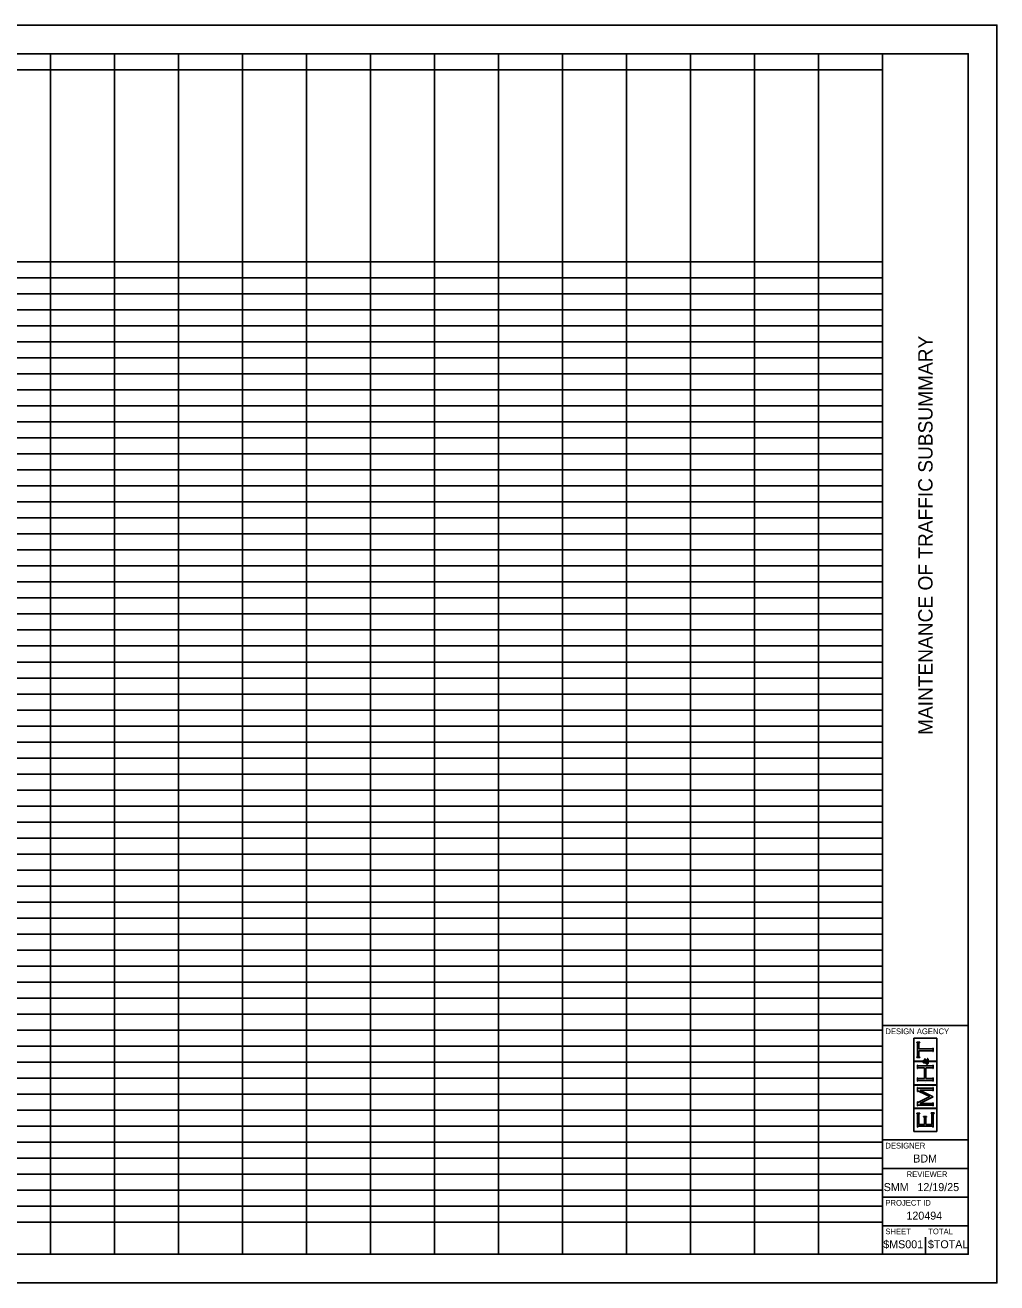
# Model space of a CAD drawing. Extents: x 0 to 34, y 0 to 22.
# Drawn here: x 17 to 34, y 0 to 22 of the extents above; entities that cross this region are included whole.
import ezdxf

# ---------------------------------------------------------------- set-up
doc = ezdxf.new("R2010")
doc.units = 0
for name, color, linetype in [('Default', 7, 'Continuous'), ('SH_Border', 7, 'Continuous'), ('SH_Cut_Line', 7, 'Continuous'), ('SH_Data', 7, 'Continuous')]:
    doc.layers.add(name, color=color, linetype=linetype)

msp = doc.modelspace()

# ---------------------------------------------------------------- linework, layer by layer
at = {"layer": 'Default'}
for p, q in [((1.5, 21.5), (32, 21.5)), ((17.442, 21.5), (17.442, 0.5)), ((18.562, 21.5), (18.562, 0.5)), ((19.681, 21.5), (19.681, 0.5)), ((20.801, 21.5), (20.801, 0.5)), ((21.921, 21.5), (21.921, 0.5)), ((23.041, 21.5), (23.041, 0.5)), ((24.161, 21.5), (24.161, 0.5)), ((25.281, 21.5), (25.281, 0.5)), ((26.401, 21.5), (26.401, 0.5)), ((27.521, 21.5), (27.521, 0.5)), ((28.64, 21.5), (28.64, 0.5)), ((29.76, 21.5), (29.76, 0.5)), ((30.88, 21.5), (30.88, 0.5)), ((32, 21.5), (32, 0.5)), ((5.123, 21.22), (32, 21.22)), ((5.123, 17.86), (32, 17.86)), ((1.5, 17.58), (32, 17.58)), ((1.5, 17.3), (32, 17.3)), ((1.5, 17.02), (32, 17.02)), ((1.5, 16.74), (32, 16.74)), ((1.5, 16.46), (32, 16.46)), ((1.5, 16.18), (32, 16.18)), ((1.5, 15.9), (32, 15.9)), ((1.5, 15.62), (32, 15.62)), ((1.5, 15.34), (32, 15.34)), ((1.5, 15.06), (32, 15.06)), ((1.5, 14.78), (32, 14.78)), ((1.5, 14.5), (32, 14.5)), ((1.5, 14.22), (32, 14.22)), ((1.5, 13.94), (32, 13.94)), ((1.5, 13.66), (32, 13.66)), ((1.5, 13.38), (32, 13.38)), ((1.5, 13.1), (32, 13.1)), ((1.5, 12.82), (32, 12.82)), ((1.5, 12.54), (32, 12.54)), ((1.5, 12.26), (32, 12.26)), ((1.5, 11.98), (32, 11.98)), ((1.5, 11.7), (32, 11.7)), ((1.5, 11.42), (32, 11.42)), ((1.5, 11.14), (32, 11.14)), ((1.5, 10.86), (32, 10.86)), ((1.5, 10.58), (32, 10.58)), ((1.5, 10.3), (32, 10.3)), ((1.5, 10.02), (32, 10.02)), ((1.5, 9.74), (32, 9.74)), ((1.5, 9.46), (32, 9.46)), ((1.5, 9.18), (32, 9.18)), ((1.5, 8.9), (32, 8.9)), ((1.5, 8.62), (32, 8.62)), ((1.5, 8.34), (32, 8.34)), ((1.5, 8.06), (32, 8.06)), ((1.5, 7.78), (32, 7.78)), ((1.5, 7.5), (32, 7.5)), ((1.5, 7.22), (32, 7.22)), ((1.5, 6.94), (32, 6.94)), ((1.5, 6.66), (32, 6.66)), ((1.5, 6.38), (32, 6.38)), ((1.5, 6.1), (32, 6.1)), ((1.5, 5.82), (32, 5.82)), ((1.5, 5.54), (32, 5.54)), ((1.5, 5.26), (32, 5.26)), ((1.5, 4.98), (32, 4.98)), ((1.5, 4.7), (32, 4.7)), ((1.5, 4.42), (32, 4.42)), ((1.5, 4.14), (32, 4.14)), ((1.5, 3.86), (32, 3.86)), ((1.5, 3.58), (32, 3.58)), ((1.5, 3.3), (32, 3.3)), ((1.5, 3.02), (32, 3.02)), ((1.5, 2.74), (32, 2.74)), ((1.5, 2.46), (32, 2.46)), ((1.5, 2.18), (32, 2.18)), ((1.5, 1.9), (32, 1.9)), ((1.5, 1.62), (32, 1.62)), ((1.5, 1.34), (32, 1.34)), ((1.5, 1.06), (32, 1.06)), ((1.5, 0.5), (32, 0.5))]:
    msp.add_line(p, q, dxfattribs=at)
at = {"layer": 'SH_Border'}
for p, q in [((32, 0.5), (32, 21.5)), ((32, 4.5), (33.5, 4.5)), ((32, 2.5), (33.5, 2.5)), ((32, 2), (33.5, 2)), ((32, 1.5), (33.5, 1.5)), ((32, 1), (33.5, 1))]:
    msp.add_line(p, q, dxfattribs=at)
msp.add_lwpolyline([(1.5, 21.5), (33.5, 21.5), (33.5, 0.5), (1.5, 0.5)], close=True, dxfattribs=at)
at = {"layer": 'SH_Cut_Line'}
msp.add_lwpolyline([(0, 0), (34, 0), (34, 22), (0, 22)], close=True, dxfattribs=at)
at = {"layer": 'SH_Data'}
for p, q in [((32.952, 4.279), (32.547, 4.279)), ((32.547, 4.279), (32.547, 3.875)), ((32.598, 4.204), (32.598, 4.211)), ((32.598, 4.211), (32.65, 4.211)), ((32.603, 4.203), (32.598, 4.204)), ((32.606, 4.201), (32.603, 4.203)), ((32.608, 4.199), (32.606, 4.201)), ((32.61, 4.196), (32.608, 4.199)), ((32.611, 4.192), (32.61, 4.196)), ((32.611, 4.187), (32.611, 4.192)), ((32.611, 3.968), (32.611, 4.187)), ((32.638, 4.196), (32.637, 4.192)), ((32.637, 4.192), (32.637, 4.187)), ((32.637, 4.187), (32.637, 4.093)), ((32.64, 4.199), (32.638, 4.196)), ((32.642, 4.201), (32.64, 4.199)), ((32.645, 4.203), (32.642, 4.201)), ((32.65, 4.204), (32.645, 4.203)), ((32.65, 4.211), (32.65, 4.204)), ((32.952, 3.875), (32.952, 4.279)), ((32.61, 3.958), (32.611, 3.962)), ((32.611, 3.962), (32.611, 3.968)), ((32.637, 4.093), (32.864, 4.093)), ((32.864, 4.061), (32.637, 4.061)), ((32.637, 4.061), (32.637, 3.968)), ((32.637, 3.968), (32.637, 3.962)), ((32.637, 3.962), (32.638, 3.958)), ((32.864, 4.093), (32.869, 4.093)), ((32.87, 4.061), (32.864, 4.061)), ((32.869, 4.093), (32.873, 4.094)), ((32.874, 4.06), (32.87, 4.061)), ((32.873, 4.094), (32.876, 4.096)), ((32.876, 4.059), (32.874, 4.06)), ((32.876, 4.096), (32.878, 4.097)), ((32.878, 4.057), (32.876, 4.059)), ((32.878, 4.097), (32.88, 4.101)), ((32.88, 4.053), (32.878, 4.057)), ((32.88, 4.101), (32.881, 4.106)), ((32.881, 4.048), (32.88, 4.053)), ((32.881, 4.106), (32.888, 4.106)), ((32.888, 4.048), (32.881, 4.048)), ((32.888, 4.106), (32.888, 4.048)), ((32.547, 3.875), (32.696, 3.875)), ((32.696, 3.869), (32.547, 3.869)), ((32.547, 3.869), (32.547, 3.465)), ((32.598, 3.95), (32.603, 3.951)), ((32.598, 3.944), (32.598, 3.95)), ((32.65, 3.944), (32.598, 3.944)), ((32.603, 3.951), (32.606, 3.953)), ((32.606, 3.953), (32.608, 3.955)), ((32.608, 3.955), (32.61, 3.958)), ((32.611, 3.749), (32.611, 3.807)), ((32.611, 3.807), (32.617, 3.807)), ((32.617, 3.749), (32.611, 3.749)), ((32.617, 3.807), (32.619, 3.802)), ((32.618, 3.754), (32.617, 3.749)), ((32.62, 3.758), (32.618, 3.754)), ((32.619, 3.802), (32.62, 3.798)), ((32.62, 3.798), (32.623, 3.797)), ((32.623, 3.76), (32.62, 3.758)), ((32.623, 3.797), (32.625, 3.795)), ((32.625, 3.761), (32.623, 3.76)), ((32.625, 3.795), (32.629, 3.794)), ((32.629, 3.762), (32.625, 3.761)), ((32.629, 3.794), (32.635, 3.794)), ((32.635, 3.762), (32.629, 3.762)), ((32.635, 3.794), (32.864, 3.794)), ((32.732, 3.762), (32.635, 3.762)), ((32.638, 3.958), (32.64, 3.955)), ((32.64, 3.955), (32.642, 3.953)), ((32.642, 3.953), (32.645, 3.951)), ((32.645, 3.951), (32.65, 3.95)), ((32.65, 3.95), (32.65, 3.944)), ((32.696, 3.875), (32.696, 3.869)), ((32.703, 3.879), (32.705, 3.883)), ((32.703, 3.873), (32.703, 3.879)), ((32.703, 3.868), (32.703, 3.873)), ((32.705, 3.863), (32.703, 3.868)), ((32.705, 3.883), (32.708, 3.887)), ((32.708, 3.858), (32.705, 3.863)), ((32.708, 3.887), (32.711, 3.89)), ((32.709, 3.879), (32.708, 3.876)), ((32.708, 3.876), (32.708, 3.873)), ((32.708, 3.873), (32.708, 3.869)), ((32.708, 3.869), (32.71, 3.866)), ((32.712, 3.853), (32.708, 3.858)), ((32.712, 3.881), (32.709, 3.879)), ((32.71, 3.866), (32.712, 3.864)), ((32.711, 3.89), (32.715, 3.892)), ((32.714, 3.883), (32.712, 3.881)), ((32.712, 3.864), (32.715, 3.862)), ((32.718, 3.85), (32.712, 3.853)), ((32.716, 3.884), (32.714, 3.883)), ((32.715, 3.892), (32.72, 3.892)), ((32.715, 3.862), (32.718, 3.861)), ((32.72, 3.884), (32.716, 3.884)), ((32.718, 3.861), (32.721, 3.861)), ((32.726, 3.85), (32.718, 3.85)), ((32.72, 3.892), (32.725, 3.892)), ((32.724, 3.884), (32.72, 3.884)), ((32.721, 3.861), (32.723, 3.861)), ((32.723, 3.861), (32.725, 3.862)), ((32.728, 3.882), (32.724, 3.884)), ((32.725, 3.892), (32.729, 3.89)), ((32.725, 3.862), (32.728, 3.862)), ((32.729, 3.85), (32.726, 3.85)), ((32.731, 3.88), (32.728, 3.882)), ((32.728, 3.862), (32.731, 3.863)), ((32.729, 3.89), (32.732, 3.887)), ((32.731, 3.85), (32.729, 3.85)), ((32.734, 3.877), (32.731, 3.88)), ((32.731, 3.863), (32.735, 3.865)), ((32.734, 3.851), (32.731, 3.85)), ((32.732, 3.887), (32.736, 3.883)), ((32.732, 3.572), (32.732, 3.762)), ((32.737, 3.872), (32.734, 3.877)), ((32.737, 3.852), (32.734, 3.851)), ((32.735, 3.865), (32.74, 3.867)), ((32.736, 3.883), (32.74, 3.878)), ((32.74, 3.867), (32.737, 3.872)), ((32.741, 3.853), (32.737, 3.852)), ((32.738, 3.893), (32.738, 3.922)), ((32.738, 3.922), (32.741, 3.922)), ((32.741, 3.893), (32.738, 3.893)), ((32.74, 3.878), (32.744, 3.869)), ((32.741, 3.922), (32.741, 3.918)), ((32.741, 3.918), (32.742, 3.915)), ((32.742, 3.896), (32.741, 3.895)), ((32.741, 3.895), (32.741, 3.893)), ((32.746, 3.855), (32.741, 3.853)), ((32.742, 3.915), (32.743, 3.913)), ((32.743, 3.897), (32.742, 3.896)), ((32.743, 3.913), (32.745, 3.911)), ((32.745, 3.899), (32.743, 3.897)), ((32.744, 3.869), (32.754, 3.875)), ((32.745, 3.911), (32.749, 3.908)), ((32.746, 3.899), (32.745, 3.899)), ((32.748, 3.899), (32.746, 3.899)), ((32.752, 3.844), (32.746, 3.855)), ((32.755, 3.899), (32.748, 3.899)), ((32.749, 3.908), (32.756, 3.904)), ((32.756, 3.86), (32.751, 3.857)), ((32.751, 3.857), (32.754, 3.852)), ((32.757, 3.837), (32.752, 3.844)), ((32.754, 3.875), (32.764, 3.881)), ((32.754, 3.852), (32.757, 3.848)), ((32.763, 3.895), (32.755, 3.899)), ((32.756, 3.904), (32.763, 3.9)), ((32.761, 3.863), (32.756, 3.86)), ((32.757, 3.848), (32.761, 3.845)), ((32.763, 3.833), (32.757, 3.837)), ((32.864, 3.762), (32.759, 3.762)), ((32.759, 3.762), (32.759, 3.572)), ((32.764, 3.865), (32.761, 3.863)), ((32.761, 3.845), (32.765, 3.843)), ((32.763, 3.9), (32.77, 3.896)), ((32.772, 3.887), (32.763, 3.895)), ((32.768, 3.829), (32.763, 3.833)), ((32.764, 3.881), (32.772, 3.887)), ((32.768, 3.867), (32.764, 3.865)), ((32.765, 3.843), (32.769, 3.841)), ((32.774, 3.872), (32.768, 3.867)), ((32.774, 3.827), (32.768, 3.829)), ((32.769, 3.841), (32.773, 3.841)), ((32.77, 3.896), (32.776, 3.891)), ((32.773, 3.841), (32.778, 3.841)), ((32.782, 3.878), (32.774, 3.872)), ((32.779, 3.827), (32.774, 3.827)), ((32.776, 3.891), (32.781, 3.895)), ((32.778, 3.841), (32.782, 3.843)), ((32.779, 3.923), (32.781, 3.926)), ((32.782, 3.922), (32.779, 3.923)), ((32.785, 3.827), (32.779, 3.827)), ((32.781, 3.926), (32.787, 3.924)), ((32.781, 3.895), (32.784, 3.898)), ((32.785, 3.921), (32.782, 3.922)), ((32.786, 3.873), (32.782, 3.878)), ((32.782, 3.843), (32.786, 3.846)), ((32.784, 3.898), (32.786, 3.901)), ((32.786, 3.919), (32.785, 3.921)), ((32.79, 3.829), (32.785, 3.827)), ((32.788, 3.917), (32.786, 3.919)), ((32.786, 3.901), (32.788, 3.904)), ((32.791, 3.886), (32.786, 3.881)), ((32.786, 3.881), (32.791, 3.876)), ((32.788, 3.869), (32.786, 3.873)), ((32.786, 3.846), (32.789, 3.849)), ((32.787, 3.924), (32.792, 3.921)), ((32.789, 3.914), (32.788, 3.917)), ((32.788, 3.904), (32.789, 3.908)), ((32.79, 3.867), (32.788, 3.869)), ((32.789, 3.911), (32.789, 3.914)), ((32.789, 3.908), (32.789, 3.911)), ((32.789, 3.849), (32.791, 3.853)), ((32.791, 3.864), (32.79, 3.867)), ((32.793, 3.834), (32.79, 3.829)), ((32.794, 3.89), (32.791, 3.886)), ((32.791, 3.876), (32.795, 3.87)), ((32.791, 3.861), (32.791, 3.864)), ((32.791, 3.859), (32.791, 3.861)), ((32.791, 3.853), (32.791, 3.859)), ((32.792, 3.921), (32.795, 3.918)), ((32.797, 3.838), (32.793, 3.834)), ((32.796, 3.894), (32.794, 3.89)), ((32.795, 3.918), (32.798, 3.914)), ((32.795, 3.87), (32.797, 3.866)), ((32.798, 3.897), (32.796, 3.894)), ((32.797, 3.866), (32.798, 3.861)), ((32.799, 3.844), (32.797, 3.838)), ((32.798, 3.914), (32.799, 3.91)), ((32.799, 3.901), (32.798, 3.897)), ((32.798, 3.861), (32.799, 3.857)), ((32.799, 3.91), (32.799, 3.905)), ((32.799, 3.905), (32.799, 3.901)), ((32.803, 3.869), (32.799, 3.875)), ((32.799, 3.875), (32.952, 3.875)), ((32.799, 3.857), (32.799, 3.852)), ((32.799, 3.852), (32.799, 3.844)), ((32.952, 3.869), (32.803, 3.869)), ((32.864, 3.794), (32.869, 3.794)), ((32.87, 3.762), (32.864, 3.762)), ((32.869, 3.794), (32.873, 3.795)), ((32.874, 3.761), (32.87, 3.762)), ((32.873, 3.795), (32.876, 3.797)), ((32.876, 3.76), (32.874, 3.761)), ((32.876, 3.797), (32.878, 3.798)), ((32.878, 3.758), (32.876, 3.76)), ((32.878, 3.798), (32.88, 3.802)), ((32.88, 3.754), (32.878, 3.758)), ((32.88, 3.802), (32.881, 3.807)), ((32.881, 3.749), (32.88, 3.754)), ((32.881, 3.807), (32.888, 3.807)), ((32.888, 3.749), (32.881, 3.749)), ((32.888, 3.807), (32.888, 3.749)), ((32.952, 3.465), (32.952, 3.869)), ((32.611, 3.527), (32.611, 3.585)), ((32.611, 3.585), (32.617, 3.585)), ((32.617, 3.527), (32.611, 3.527)), ((32.617, 3.585), (32.619, 3.58)), ((32.618, 3.532), (32.617, 3.527)), ((32.62, 3.536), (32.618, 3.532)), ((32.619, 3.58), (32.62, 3.576)), ((32.62, 3.576), (32.623, 3.574)), ((32.623, 3.537), (32.62, 3.536)), ((32.623, 3.574), (32.625, 3.573)), ((32.625, 3.539), (32.623, 3.537)), ((32.625, 3.573), (32.629, 3.572)), ((32.629, 3.54), (32.625, 3.539)), ((32.629, 3.572), (32.635, 3.572)), ((32.635, 3.54), (32.629, 3.54)), ((32.635, 3.572), (32.732, 3.572)), ((32.864, 3.54), (32.635, 3.54)), ((32.759, 3.572), (32.864, 3.572)), ((32.864, 3.572), (32.87, 3.572)), ((32.87, 3.54), (32.864, 3.54)), ((32.87, 3.572), (32.874, 3.573)), ((32.874, 3.539), (32.87, 3.54)), ((32.874, 3.573), (32.876, 3.574)), ((32.876, 3.538), (32.874, 3.539)), ((32.876, 3.574), (32.878, 3.576)), ((32.878, 3.536), (32.876, 3.538)), ((32.878, 3.576), (32.88, 3.58)), ((32.88, 3.532), (32.878, 3.536)), ((32.88, 3.58), (32.881, 3.585)), ((32.881, 3.527), (32.88, 3.532)), ((32.881, 3.585), (32.888, 3.585)), ((32.888, 3.527), (32.881, 3.527)), ((32.888, 3.585), (32.888, 3.527)), ((32.547, 3.465), (32.952, 3.465)), ((32.952, 3.459), (32.547, 3.459)), ((32.547, 3.459), (32.547, 3.055)), ((32.611, 3.345), (32.611, 3.418)), ((32.611, 3.418), (32.617, 3.418)), ((32.617, 3.345), (32.611, 3.345)), ((32.617, 3.418), (32.619, 3.412)), ((32.62, 3.352), (32.617, 3.345)), ((32.619, 3.412), (32.62, 3.409)), ((32.62, 3.409), (32.623, 3.407)), ((32.622, 3.355), (32.62, 3.352)), ((32.626, 3.355), (32.622, 3.355)), ((32.623, 3.407), (32.625, 3.405)), ((32.625, 3.405), (32.629, 3.405)), ((32.629, 3.355), (32.626, 3.355)), ((32.629, 3.405), (32.635, 3.405)), ((32.633, 3.353), (32.629, 3.355)), ((32.64, 3.35), (32.633, 3.353)), ((32.635, 3.405), (32.864, 3.405)), ((32.825, 3.257), (32.64, 3.35)), ((32.864, 3.373), (32.654, 3.373)), ((32.654, 3.373), (32.888, 3.255)), ((32.75, 3.5), (32.75, 3.5)), ((32.864, 3.405), (32.869, 3.405)), ((32.87, 3.373), (32.864, 3.373)), ((32.869, 3.405), (32.873, 3.405)), ((32.874, 3.372), (32.87, 3.373)), ((32.873, 3.405), (32.876, 3.407)), ((32.876, 3.37), (32.874, 3.372)), ((32.876, 3.407), (32.878, 3.409)), ((32.878, 3.369), (32.876, 3.37)), ((32.878, 3.409), (32.88, 3.412)), ((32.88, 3.365), (32.878, 3.369)), ((32.88, 3.412), (32.881, 3.418)), ((32.881, 3.36), (32.88, 3.365)), ((32.881, 3.418), (32.888, 3.418)), ((32.888, 3.36), (32.881, 3.36)), ((32.888, 3.418), (32.888, 3.36)), ((32.952, 3.055), (32.952, 3.459)), ((32.611, 3.096), (32.611, 3.168)), ((32.611, 3.168), (32.617, 3.168)), ((32.617, 3.096), (32.611, 3.096)), ((32.617, 3.168), (32.62, 3.162)), ((32.618, 3.102), (32.617, 3.096)), ((32.62, 3.105), (32.618, 3.102)), ((32.62, 3.162), (32.622, 3.158)), ((32.623, 3.107), (32.62, 3.105)), ((32.622, 3.158), (32.626, 3.158)), ((32.625, 3.109), (32.623, 3.107)), ((32.629, 3.109), (32.625, 3.109)), ((32.626, 3.158), (32.627, 3.158)), ((32.627, 3.158), (32.633, 3.161)), ((32.635, 3.109), (32.629, 3.109)), ((32.633, 3.161), (32.641, 3.165)), ((32.864, 3.109), (32.635, 3.109)), ((32.641, 3.165), (32.825, 3.257)), ((32.888, 3.255), (32.654, 3.138)), ((32.654, 3.138), (32.864, 3.138)), ((32.864, 3.138), (32.869, 3.138)), ((32.87, 3.109), (32.864, 3.109)), ((32.869, 3.138), (32.873, 3.139)), ((32.874, 3.109), (32.87, 3.109)), ((32.873, 3.139), (32.876, 3.141)), ((32.876, 3.107), (32.874, 3.109)), ((32.876, 3.141), (32.878, 3.143)), ((32.878, 3.105), (32.876, 3.107)), ((32.878, 3.143), (32.88, 3.146)), ((32.88, 3.102), (32.878, 3.105)), ((32.88, 3.146), (32.881, 3.151)), ((32.881, 3.096), (32.88, 3.102)), ((32.881, 3.151), (32.888, 3.151)), ((32.888, 3.096), (32.881, 3.096)), ((32.888, 3.151), (32.888, 3.096)), ((32.547, 3.055), (32.952, 3.055)), ((32.952, 3.049), (32.547, 3.049)), ((32.547, 3.049), (32.547, 2.645)), ((32.598, 2.962), (32.598, 2.969)), ((32.598, 2.969), (32.65, 2.969)), ((32.603, 2.961), (32.598, 2.962)), ((32.606, 2.959), (32.603, 2.961)), ((32.608, 2.957), (32.606, 2.959)), ((32.61, 2.955), (32.608, 2.957)), ((32.611, 2.951), (32.61, 2.955)), ((32.611, 2.945), (32.611, 2.951)), ((32.611, 2.725), (32.611, 2.945)), ((32.64, 2.957), (32.638, 2.955)), ((32.638, 2.955), (32.638, 2.951)), ((32.638, 2.951), (32.638, 2.945)), ((32.638, 2.945), (32.638, 2.77)), ((32.642, 2.959), (32.64, 2.957)), ((32.645, 2.961), (32.642, 2.959)), ((32.65, 2.962), (32.645, 2.961)), ((32.65, 2.969), (32.65, 2.962)), ((32.719, 2.902), (32.719, 2.908)), ((32.719, 2.908), (32.772, 2.908)), ((32.724, 2.901), (32.719, 2.902)), ((32.728, 2.899), (32.724, 2.901)), ((32.729, 2.896), (32.728, 2.899)), ((32.731, 2.894), (32.729, 2.896)), ((32.732, 2.89), (32.731, 2.894)), ((32.732, 2.884), (32.732, 2.89)), ((32.732, 2.77), (32.732, 2.884)), ((32.76, 2.894), (32.759, 2.89)), ((32.759, 2.89), (32.759, 2.884)), ((32.759, 2.884), (32.759, 2.77)), ((32.761, 2.896), (32.76, 2.894)), ((32.763, 2.899), (32.761, 2.896)), ((32.767, 2.901), (32.763, 2.899)), ((32.772, 2.902), (32.767, 2.901)), ((32.772, 2.908), (32.772, 2.902)), ((32.848, 2.965), (32.848, 2.972)), ((32.848, 2.972), (32.901, 2.972)), ((32.853, 2.964), (32.848, 2.965)), ((32.857, 2.962), (32.853, 2.964)), ((32.859, 2.96), (32.857, 2.962)), ((32.86, 2.958), (32.859, 2.96)), ((32.861, 2.953), (32.86, 2.958)), ((32.861, 2.948), (32.861, 2.953)), ((32.861, 2.77), (32.861, 2.948)), ((32.889, 2.957), (32.888, 2.953)), ((32.888, 2.953), (32.888, 2.948)), ((32.888, 2.948), (32.888, 2.725)), ((32.891, 2.96), (32.889, 2.957)), ((32.892, 2.962), (32.891, 2.96)), ((32.896, 2.964), (32.892, 2.962)), ((32.901, 2.965), (32.896, 2.964)), ((32.901, 2.972), (32.901, 2.965)), ((32.952, 2.645), (32.952, 3.049)), ((32.547, 2.645), (32.952, 2.645)), ((32.617, 2.725), (32.611, 2.725)), ((32.619, 2.73), (32.617, 2.725)), ((32.62, 2.734), (32.619, 2.73)), ((32.623, 2.735), (32.62, 2.734)), ((32.625, 2.737), (32.623, 2.735)), ((32.629, 2.738), (32.625, 2.737)), ((32.635, 2.738), (32.629, 2.738)), ((32.864, 2.738), (32.635, 2.738)), ((32.638, 2.77), (32.732, 2.77)), ((32.759, 2.77), (32.861, 2.77)), ((32.87, 2.738), (32.864, 2.738)), ((32.874, 2.737), (32.87, 2.738)), ((32.876, 2.735), (32.874, 2.737)), ((32.878, 2.734), (32.876, 2.735)), ((32.88, 2.73), (32.878, 2.734)), ((32.881, 2.725), (32.88, 2.73)), ((32.888, 2.725), (32.881, 2.725)), ((32.375, 0.675), (32.375, 0.675)), ((32.75, 0.5), (32.75, 0.8))]:
    msp.add_line(p, q, dxfattribs=at)

# ---------------------------------------------------------------- texts
msp.add_text('MAINTENANCE OF TRAFFIC SUBSUMMARY', height=0.25, rotation=90, dxfattribs=at).set_placement((32.875, 9.584))
for s, height, p in [('DESIGN AGENCY', 0.1, (32.05, 4.35)), ('DESIGNER', 0.1, (32.05, 2.35)), ('BDM', 0.14, (32.537, 2.105)), ('REVIEWER', 0.1, (32.422, 1.85)), ('SMM', 0.14, (32.02, 1.605)), ('12/19/25', 0.14, (32.611, 1.605)), ('PROJECT ID', 0.1, (32.05, 1.35)), ('120494', 0.14, (32.418, 1.105)), ('SHEET', 0.1, (32.05, 0.85)), ('TOTAL', 0.1, (32.8, 0.85)), ('$MS001', 0.14, (32.013, 0.605)), ('$TOTAL', 0.14, (32.794, 0.605))]:
    msp.add_text(s, height=height, dxfattribs=at).set_placement(p)

doc.saveas('drawing.dxf')
